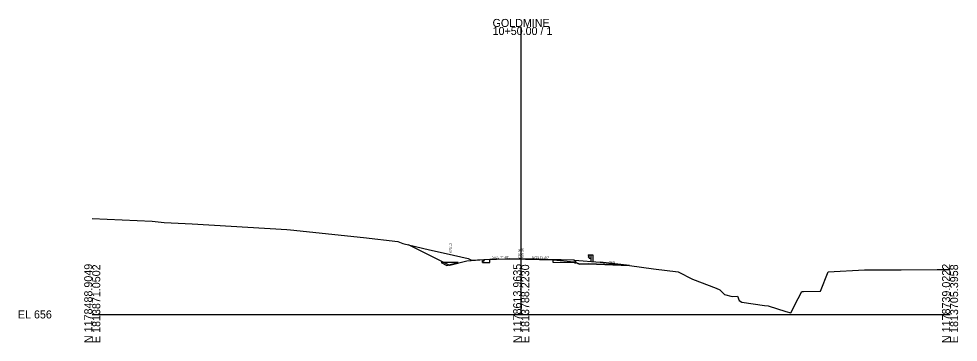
# Model space of a CAD drawing. Extents: x -26 to 1603, y -10 to 1590.
# Drawn here: x 1274.3 to 1602.8, y -9.7 to 103.3 of the extents above; entities that cross this region are included whole.
import ezdxf

# ---------------------------------------------------------------- set-up
doc = ezdxf.new("R2010")
doc.units = 0
for name, color, linetype in [('Default', 7, 'Continuous'), ('RD_GPK_XS_Cell', 7, 'Continuous'), ('RD_XS_Base', 7, 'Continuous'), ('RD_XS_EarthShd', 7, 'Continuous'), ('RD_XS_ExGround', 7, 'Continuous'), ('RD_XS_GR', 7, 'Continuous'), ('RD_XS_Misc_Line', 7, 'Continuous'), ('RD_XS_Pave', 7, 'Continuous'), ('RD_XS_TieSlope', 7, 'Continuous'), ('RD_XS_TX_Elev_EX', 7, 'Continuous'), ('RD_XS_TX_Elev_PR', 7, 'Continuous'), ('RD_XS_TX_Slope', 7, 'Continuous')]:
    doc.layers.add(name, color=color, linetype=linetype)

msp = doc.modelspace()

# ---------------------------------------------------------------- linework, layer by layer
at = {"layer": 'Default'}
for p, q in [((1450, 19.39), (1437, 19.12)), ((1468.6, 19), (1450, 19.39))]:
    msp.add_line(p, q, dxfattribs=at)
at = {"layer": 'RD_GPK_XS_Cell'}
for p, q in [((1450, 0), (1450, 100.41)), ((1300, 0), (1450, 0)), ((1450, 0), (1600, 0))]:
    msp.add_line(p, q, dxfattribs=at)
at = {"layer": 'RD_XS_Base'}
for p, q in [((1437, 18.12), (1439.08, 18.16)), ((1439.08, 18.16), (1439.08, 19.31)), ((1461.21, 18.16), (1461.21, 19.08)), ((1468.6, 18), (1461.21, 18.16))]:
    msp.add_line(p, q, dxfattribs=at)
at = {"layer": 'RD_XS_EarthShd'}
for p, q in [((1437, 19.12), (1431, 18.62)), ((1468.6, 19), (1477.6, 18.25))]:
    msp.add_line(p, q, dxfattribs=at)
at = {"layer": 'RD_XS_ExGround'}
msp.add_lwpolyline([(1300, 33.47), (1320.92, 32.57), (1325.12, 32.13), (1334.89, 31.7), (1367.99, 29.66), (1369.35, 29.58), (1394.87, 26.87), (1406.92, 25.49), (1408.61, 24.8), (1417.96, 22.58), (1423.72, 21.3), (1431.49, 19.52), (1432.67, 18.95), (1439.08, 19.31), (1450, 19.39), (1450.37, 19.39), (1450.74, 19.38), (1461.21, 19.08), (1468.51, 18.39), (1470.45, 17.58), (1473.47, 17.73), (1487.93, 17.04), (1496.27, 15.96), (1504.94, 14.9), (1509.93, 12.3), (1518.19, 9.15), (1519.47, 8.55), (1521.16, 6.97), (1523.79, 6.28), (1525.62, 6.4), (1526.19, 4.85), (1527.14, 4.34), (1535.12, 3.11), (1536.38, 2.97), (1542.51, 0.99), (1544.28, 0.59), (1546.83, 5.6), (1548.19, 7.99), (1548.68, 7.99), (1554.72, 8.18), (1557.39, 14.93), (1570.02, 15.62), (1582.9, 15.63), (1595.52, 15.66), (1600, 15.66)], dxfattribs=at)
at = {"layer": 'RD_XS_GR'}
for p, q in [((1473.74, 20.77), (1473.46, 20.57)), ((1473.46, 20.57), (1473.46, 20.52)), ((1473.46, 20.52), (1473.74, 20.32)), ((1473.46, 20), (1473.74, 20.2)), ((1473.46, 19.95), (1473.46, 20)), ((1473.74, 19.75), (1473.46, 19.95)), ((1473.74, 20.85), (1474.4, 20.85)), ((1473.74, 19.68), (1473.74, 20.85)), ((1474.4, 20.85), (1475.07, 20.85)), ((1474.4, 20.85), (1474.4, 18.52)), ((1475.07, 20.85), (1475.07, 18.46)), ((1428, 18.1), (1422, 18.1)), ((1422, 18.1), (1424, 17.1)), ((1424, 17.1), (1428, 18.1)), ((1473.74, 19.68), (1474.4, 19.68))]:
    msp.add_line(p, q, dxfattribs=at)
at = {"layer": 'RD_XS_Misc_Line'}
for points in [[(1437, 19.12), (1431, 18.62), (1425, 17.12), (1410.56, 24.34), (1417.96, 22.58), (1423.72, 21.3), (1431.49, 19.52), (1432.67, 18.95), (1439.08, 19.31), (1439.08, 19.16)], [(1437, 18.12), (1439.08, 18.16), (1439.08, 19.16), (1437, 19.12), (1437, 18.79), (1436.5, 18.78), (1436.5, 18.11)], [(1450, 19.39), (1439.08, 19.16), (1439.08, 19.31)], [(1450, 19.39), (1450.37, 19.39), (1450.74, 19.38), (1451.51, 19.36)], [(1469.1, 18.66), (1468.6, 18.67), (1468.6, 19), (1451.51, 19.36), (1461.21, 19.08), (1468.51, 18.39), (1469.1, 18.14)], [(1461.21, 18.16), (1461.21, 19.08), (1468.51, 18.39), (1469.1, 18.14), (1469.1, 17.99), (1468.6, 18)], [(1468.6, 19), (1477.6, 18.25), (1487.93, 17.04), (1473.47, 17.73), (1470.45, 17.58), (1469.1, 18.14), (1469.1, 18.66), (1468.6, 18.67)]]:
    msp.add_lwpolyline(points, close=True, dxfattribs=at)
at = {"layer": 'RD_XS_Pave'}
for p, q in [((1436.5, 18.78), (1437, 18.79)), ((1436.5, 18.11), (1436.5, 18.78)), ((1437, 18.12), (1436.5, 18.11)), ((1437, 18.79), (1437, 19.12)), ((1468.6, 18.67), (1468.6, 19)), ((1469.1, 18.66), (1468.6, 18.67)), ((1468.6, 18), (1469.1, 17.99)), ((1469.1, 17.99), (1469.1, 18.66))]:
    msp.add_line(p, q, dxfattribs=at)
at = {"layer": 'RD_XS_TieSlope'}
msp.add_line((1487.93, 17.04), (1477.6, 18.25), dxfattribs=at)

# ---------------------------------------------------------------- texts
at = {"layer": 'Default'}
msp.add_text(' 675.39', height=0.8, rotation=90, dxfattribs=at).set_placement((1450.91, 19.39))
at = {"layer": 'RD_GPK_XS_Cell'}
for s, p in [('GOLDMINE', (1440, 100.41)), ('10+50.00 / 1', (1440, 97.61)), ('EL 656', (1274, -1.4))]:
    msp.add_text(s, height=2.8, dxfattribs=at).set_placement(p)
for s, p in [('N 1178488.9049', (1300, -10)), ('E 1813871.0502', (1302.8, -10)), ('N 1178613.9635', (1450, -10)), ('E 1813788.2230', (1452.8, -10)), ('N 1178739.0222', (1600, -10)), ('E 1813705.3958', (1602.8, -10))]:
    msp.add_text(s, height=2.8, rotation=90, dxfattribs=at).set_placement(p)
at = {"layer": 'RD_XS_TX_Elev_EX'}
msp.add_text('675.39', height=0.8, rotation=90, dxfattribs=at).set_placement((1449.92, 19.55))
at = {"layer": 'RD_XS_TX_Elev_PR'}
msp.add_text('673.12', height=0.8, rotation=90, dxfattribs=at).set_placement((1425.72, 21.55))
at = {"layer": 'RD_XS_TX_Slope'}
for s, rotation, p in [('0.021 FT./FT.', 1.1916, (1439.71, 19.43)), ('0.021 FT./FT.', 358.8084, (1453.72, 19.56)), ('VAR.', 353.1002, (1480.69, 17.97))]:
    msp.add_text(s, height=0.75, rotation=rotation, dxfattribs=at).set_placement(p)

doc.saveas('drawing.dxf')
